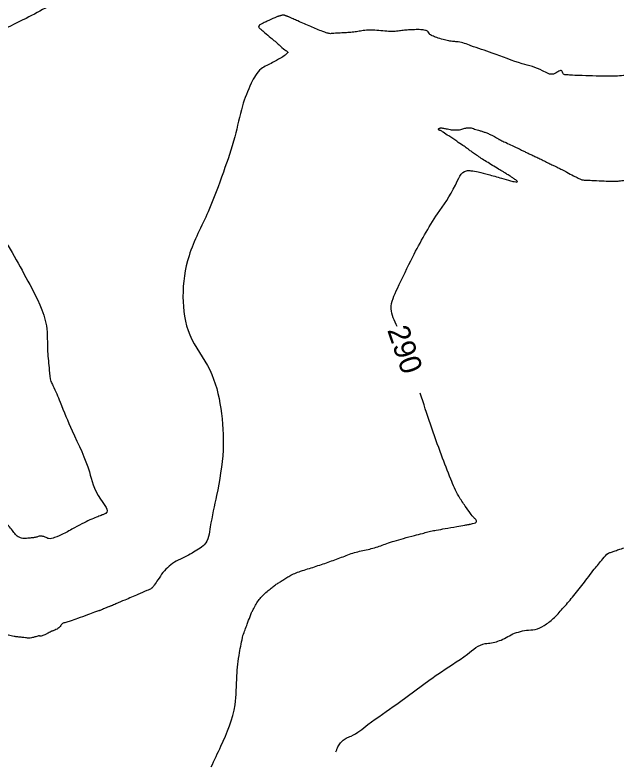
# Model space of a CAD drawing. Extents: x -478102 to -473059, y -1117705 to -1114104.
# Drawn here: x -473738.9 to -473628, y -1115846.1 to -1115707.5 of the extents above; entities that cross this region are included whole.
import ezdxf

# ---------------------------------------------------------------- set-up
doc = ezdxf.new("R2010")
doc.units = 0
for name, color, linetype in [('Vrstevnice_hlavni', 7, 'Continuous'), ('Vrstevnice_popis', 7, 'Continuous'), ('Vrstevnice_vedlejsi', 7, 'Continuous')]:
    doc.layers.add(name, color=color, linetype=linetype)

msp = doc.modelspace()

# ---------------------------------------------------------------- linework, layer by layer
at = {"layer": 'Vrstevnice_hlavni'}
for points in [[(-473628.006, -1115738.135), (-473627.612, -1115738.099), (-473627.098, -1115738.032), (-473626.465, -1115737.934), (-473625.712, -1115737.805), (-473625.126, -1115737.782), (-473624.706, -1115737.864), (-473624.453, -1115738.052), (-473624.056, -1115738.214), (-473623.515, -1115738.351), (-473622.831, -1115738.463), (-473621.977, -1115738.469), (-473620.952, -1115738.369), (-473619.758, -1115738.165), (-473618.673, -1115738.111), (-473617.699, -1115738.207), (-473616.834, -1115738.454), (-473616.07, -1115738.658), (-473615.408, -1115738.821), (-473614.847, -1115738.942), (-473614.352, -1115739.074), (-473613.922, -1115739.217), (-473613.557, -1115739.371), (-473612.986, -1115739.209), (-473612.207, -1115738.733), (-473611.221, -1115737.941), (-473610.493, -1115737.443), (-473610.022, -1115737.238), (-473609.808, -1115737.326), (-473609.65, -1115737.41), (-473609.546, -1115737.488), (-473609.498, -1115737.562), (-473609.448, -1115737.617), (-473609.396, -1115737.653), (-473609.344, -1115737.671), (-473609.284, -1115737.672), (-473609.218, -1115737.658), (-473609.145, -1115737.627), (-473608.356, -1115736.058), (-473606.851, -1115732.95), (-473604.63, -1115728.305), (-473603.008, -1115724.936), (-473601.984, -1115722.844), (-473601.559, -1115722.028), (-473601.248, -1115721.4), (-473601.05, -1115720.96), (-473600.966, -1115720.709), (-473600.877, -1115720.483), (-473600.783, -1115720.283), (-473600.684, -1115720.109), (-473600.609, -1115719.949), (-473600.556, -1115719.804), (-473600.527, -1115719.673), (-473600.49, -1115719.559), (-473600.444, -1115719.462), (-473600.39, -1115719.382), (-473600.339, -1115719.311), (-473600.289, -1115719.249), (-473600.241, -1115719.196), (-473600.189, -1115719.143), (-473600.134, -1115719.089), (-473600.075, -1115719.035), (-473597.757, -1115717.837), (-473593.181, -1115715.494), (-473586.346, -1115712.008), (-473581.479, -1115709.455), (-473578.578, -1115707.835), (-473577.645, -1115707.15), (-473575.166, -1115704.463), (-473571.141, -1115699.773), (-473565.57, -1115693.081), (-473560.969, -1115687.91), (-473557.338, -1115684.26), (-473554.675, -1115682.13), (-473549.56, -1115676.892), (-473541.991, -1115668.546), (-473521.947, -1115645.639)], [(-473668.475, -1115764.94), (-473669.605, -1115761.647), (-473668.466, -1115757.907), (-473665.623, -1115752.073), (-473661.076, -1115744.146), (-473657.776, -1115738.858), (-473655.721, -1115736.21), (-473654.914, -1115736.201), (-473653.575, -1115736.429), (-473651.704, -1115736.894), (-473649.302, -1115737.597), (-473647.612, -1115738.06), (-473646.634, -1115738.281), (-473646.367, -1115738.262), (-473646.375, -1115738.128), (-473646.657, -1115737.88), (-473647.213, -1115737.517), (-473647.682, -1115737.215), (-473648.063, -1115736.972), (-473648.357, -1115736.788), (-473648.938, -1115736.434), (-473649.808, -1115735.909), (-473650.964, -1115735.213), (-473652.028, -1115734.55), (-473652.998, -1115733.922), (-473653.874, -1115733.327), (-473654.6, -1115732.825), (-473655.176, -1115732.414), (-473655.602, -1115732.096), (-473656.384, -1115731.553), (-473657.521, -1115730.786), (-473659.012, -1115729.793), (-473660.021, -1115729.128), (-473660.547, -1115728.79), (-473660.59, -1115728.78), (-473660.64, -1115728.768), (-473660.697, -1115728.755), (-473660.76, -1115728.74), (-473660.811, -1115728.706), (-473660.849, -1115728.655), (-473660.874, -1115728.584), (-473660.891, -1115728.534), (-473660.901, -1115728.503), (-473660.902, -1115728.491), (-473660.859, -1115728.463), (-473660.772, -1115728.42), (-473660.641, -1115728.361), (-473660.545, -1115728.32), (-473660.483, -1115728.298), (-473660.457, -1115728.293), (-473660.122, -1115728.349), (-473659.479, -1115728.466), (-473658.528, -1115728.643), (-473657.634, -1115728.689), (-473656.799, -1115728.604), (-473656.021, -1115728.388), (-473655.373, -1115728.29), (-473654.853, -1115728.309), (-473654.462, -1115728.446), (-473654.01, -1115728.593), (-473653.495, -1115728.749), (-473652.919, -1115728.915), (-473652.323, -1115729.124), (-473651.706, -1115729.374), (-473651.069, -1115729.666), (-473650.567, -1115729.913), (-473650.201, -1115730.115), (-473649.972, -1115730.272), (-473649.799, -1115730.385), (-473649.683, -1115730.454), (-473649.625, -1115730.48), (-473649.21, -1115730.673), (-473648.44, -1115731.034), (-473647.313, -1115731.564), (-473646.364, -1115732.015), (-473645.592, -1115732.388), (-473644.997, -1115732.682), (-473644.364, -1115732.989), (-473643.694, -1115733.307), (-473642.987, -1115733.638), (-473642.226, -1115734.002), (-473641.409, -1115734.399), (-473640.537, -1115734.83), (-473639.818, -1115735.182), (-473639.254, -1115735.457), (-473638.844, -1115735.655), (-473638.166, -1115736), (-473637.219, -1115736.492), (-473636.005, -1115737.132), (-473635.131, -1115737.576), (-473634.598, -1115737.825), (-473634.405, -1115737.877), (-473633.631, -1115737.938), (-473632.275, -1115738.01), (-473630.338, -1115738.09), (-473628.914, -1115738.132), (-473628.006, -1115738.135)], [(-473696.917, -1115821.862), (-473696.136, -1115819.764), (-473695.615, -1115818.364), (-473695.354, -1115817.661), (-473695.352, -1115817.656), (-473695.186, -1115817.356), (-473694.858, -1115816.76), (-473694.366, -1115815.869), (-473693.773, -1115815.046), (-473693.078, -1115814.29), (-473692.282, -1115813.603), (-473691.56, -1115813.018), (-473690.913, -1115812.535), (-473690.34, -1115812.154), (-473689.714, -1115811.749), (-473689.037, -1115811.32), (-473688.307, -1115810.866), (-473687.391, -1115810.43), (-473686.291, -1115810.013), (-473685.005, -1115809.613), (-473683.728, -1115809.204), (-473682.459, -1115808.785), (-473681.2, -1115808.357), (-473679.968, -1115807.915), (-473678.763, -1115807.46), (-473677.585, -1115806.992), (-473676.377, -1115806.594), (-473675.14, -1115806.266), (-473673.873, -1115806.008), (-473672.665, -1115805.697), (-473671.515, -1115805.332), (-473670.424, -1115804.915), (-473669.029, -1115804.461), (-473667.331, -1115803.969), (-473665.33, -1115803.441), (-473663.831, -1115803.046), (-473662.834, -1115802.786), (-473662.341, -1115802.659), (-473661.291, -1115802.45), (-473659.685, -1115802.159), (-473657.523, -1115801.785), (-473656.056, -1115801.531), (-473655.283, -1115801.395), (-473655.205, -1115801.378), (-473654.978, -1115801.323), (-473654.602, -1115801.231), (-473654.077, -1115801.1), (-473653.858, -1115800.887), (-473653.945, -1115800.591), (-473654.338, -1115800.213), (-473655.005, -1115799.355), (-473655.945, -1115798.017), (-473657.159, -1115796.2), (-473658.623, -1115793.079), (-473660.337, -1115788.654), (-473664.268, -1115777.198)], [(-473702.787, -1115846.101), (-473700.971, -1115842.26), (-473698.38, -1115834.653), (-473698.038, -1115829.307), (-473697.55, -1115825.043), (-473696.917, -1115821.862)]]:
    msp.add_spline(points, degree=3, dxfattribs=at)
at = {"layer": 'Vrstevnice_vedlejsi'}
for points in [[(-473633.827, -1115698.259), (-473633.995, -1115698.089), (-473634.23, -1115697.875), (-473634.531, -1115697.615), (-473634.898, -1115697.311), (-473635.37, -1115696.943), (-473635.946, -1115696.512), (-473636.626, -1115696.016), (-473637.283, -1115695.777), (-473637.916, -1115695.795), (-473638.526, -1115696.069), (-473639.188, -1115696.16), (-473639.902, -1115696.067), (-473640.669, -1115695.791), (-473641.217, -1115695.604), (-473641.547, -1115695.506), (-473641.658, -1115695.498), (-473641.786, -1115695.477), (-473641.93, -1115695.443), (-473642.092, -1115695.396), (-473642.453, -1115694.901), (-473643.014, -1115693.955), (-473643.775, -1115692.561), (-473644.339, -1115691.631), (-473644.706, -1115691.167), (-473644.878, -1115691.166), (-473646.367, -1115691.372), (-473649.174, -1115691.783), (-473653.299, -1115692.4), (-473658.302, -1115692.607), (-473664.183, -1115692.403), (-473670.942, -1115691.788), (-473675.569, -1115691.399), (-473678.062, -1115691.235), (-473678.423, -1115691.297), (-473678.805, -1115691.345), (-473679.208, -1115691.38), (-473679.634, -1115691.402), (-473680.115, -1115691.437), (-473680.652, -1115691.486), (-473681.245, -1115691.548), (-473681.804, -1115691.615), (-473682.327, -1115691.685), (-473682.816, -1115691.76), (-473683.401, -1115691.864), (-473684.081, -1115691.997), (-473684.858, -1115692.16), (-473685.679, -1115692.274), (-473686.545, -1115692.337), (-473687.456, -1115692.35), (-473688.562, -1115692.464), (-473689.863, -1115692.678), (-473691.359, -1115692.993), (-473692.754, -1115693.224), (-473694.047, -1115693.371), (-473695.239, -1115693.435), (-473696.867, -1115693.593), (-473698.93, -1115693.846), (-473701.429, -1115694.194), (-473703.483, -1115694.472), (-473705.093, -1115694.682), (-473706.258, -1115694.823), (-473707.349, -1115694.783), (-473708.365, -1115694.561), (-473709.307, -1115694.159), (-473710.077, -1115693.846), (-473710.676, -1115693.62), (-473711.103, -1115693.484), (-473711.702, -1115693.27), (-473712.474, -1115692.98), (-473713.418, -1115692.614), (-473714.211, -1115692.359), (-473714.854, -1115692.217), (-473715.347, -1115692.188), (-473715.74, -1115692.15), (-473716.036, -1115692.105), (-473716.232, -1115692.052), (-473716.416, -1115692.058), (-473716.587, -1115692.125), (-473716.745, -1115692.251), (-473717.14, -1115692.449), (-473717.774, -1115692.717), (-473718.644, -1115693.057), (-473719.102, -1115693.587), (-473719.147, -1115694.306), (-473718.779, -1115695.214), (-473718.469, -1115695.982), (-473718.217, -1115696.61), (-473718.023, -1115697.097), (-473718.112, -1115697.585), (-473718.484, -1115698.074), (-473719.139, -1115698.564), (-473720.229, -1115699.239), (-473721.756, -1115700.099), (-473723.718, -1115701.144), (-473728.761, -1115703.819), (-473736.885, -1115708.126)], [(-473736.885, -1115708.126), (-473748.09, -1115714.063), (-473755.581, -1115718.079), (-473759.357, -1115720.173), (-473759.419, -1115720.346), (-473756.562, -1115724.848), (-473750.785, -1115733.68), (-473742.09, -1115746.84), (-473736.212, -1115757.206), (-473733.15, -1115764.778), (-473732.905, -1115769.555), (-473732.619, -1115772.989), (-473732.294, -1115775.077), (-473731.928, -1115775.821), (-473730.626, -1115778.839), (-473728.388, -1115784.131), (-473725.214, -1115791.696), (-473723.155, -1115796.772), (-473722.21, -1115799.358), (-473722.38, -1115799.453), (-473722.861, -1115799.66), (-473723.653, -1115799.979), (-473724.757, -1115800.409), (-473726.186, -1115801.082), (-473727.942, -1115801.998), (-473730.024, -1115803.157), (-473731.621, -1115803.832), (-473732.733, -1115804.022), (-473733.358, -1115803.727), (-473733.929, -1115803.579), (-473734.443, -1115803.577), (-473734.903, -1115803.722), (-473735.531, -1115803.839), (-473736.329, -1115803.931), (-473737.296, -1115803.995), (-473738.129, -1115803.776), (-473738.829, -1115803.274), (-473739.395, -1115802.488), (-473740.125, -1115801.665), (-473741.02, -1115800.805), (-473742.08, -1115799.908), (-473743.23, -1115799.265), (-473744.471, -1115798.874), (-473745.803, -1115798.738), (-473746.741, -1115798.646), (-473747.284, -1115798.6), (-473747.433, -1115798.6), (-473747.65, -1115798.58), (-473747.934, -1115798.539), (-473748.285, -1115798.478), (-473748.767, -1115798.655), (-473749.38, -1115799.07), (-473750.123, -1115799.723), (-473750.726, -1115800.236), (-473751.186, -1115800.608), (-473751.506, -1115800.838), (-473752.388, -1115800.662), (-473753.831, -1115800.08), (-473755.837, -1115799.09), (-473758.181, -1115797.917), (-473760.863, -1115796.56), (-473763.884, -1115795.021), (-473766.014, -1115793.92), (-473767.255, -1115793.257), (-473767.606, -1115793.033), (-473768.384, -1115792.504), (-473769.588, -1115791.67), (-473771.218, -1115790.531), (-473772.894, -1115789.612), (-473774.616, -1115788.914), (-473776.384, -1115788.436), (-473778.175, -1115788.351), (-473779.988, -1115788.658), (-473781.825, -1115789.358), (-473783.761, -1115789.804), (-473785.796, -1115789.996), (-473787.932, -1115789.933), (-473790.24, -1115789.962), (-473792.721, -1115790.082), (-473795.375, -1115790.292), (-473798.082, -1115790.485), (-473800.842, -1115790.659), (-473803.656, -1115790.816), (-473805.574, -1115790.922), (-473806.597, -1115790.978), (-473806.725, -1115790.983), (-473806.818, -1115790.988), (-473806.878, -1115790.99), (-473806.903, -1115790.991), (-473807.545, -1115790.98), (-473808.802, -1115790.958), (-473810.676, -1115790.923), (-473812.576, -1115790.887), (-473814.501, -1115790.848), (-473816.452, -1115790.809), (-473818.119, -1115790.836), (-473819.503, -1115790.932)], [(-473691.064, -1115708.023), (-473691.409, -1115708.174), (-473691.88, -1115708.387), (-473692.476, -1115708.662), (-473693.198, -1115709), (-473693.68, -1115709.247), (-473693.923, -1115709.404), (-473693.925, -1115709.47), (-473693.945, -1115709.533), (-473693.98, -1115709.593), (-473694.033, -1115709.651), (-473693.988, -1115709.76), (-473693.846, -1115709.921), (-473693.606, -1115710.133), (-473692.924, -1115710.722), (-473691.8, -1115711.686), (-473690.233, -1115713.028), (-473689.187, -1115713.927), (-473688.661, -1115714.383), (-473688.655, -1115714.398), (-473688.735, -1115714.488), (-473688.9, -1115714.655), (-473689.149, -1115714.899), (-473690.007, -1115715.442), (-473691.473, -1115716.286), (-473693.546, -1115717.429), (-473695.395, -1115720.087), (-473697.017, -1115724.258), (-473698.415, -1115729.943), (-473700.519, -1115736.441), (-473703.332, -1115743.752), (-473706.852, -1115751.876), (-473707.978, -1115759.446), (-473706.71, -1115766.462), (-473703.048, -1115772.924), (-473701.007, -1115780.007), (-473700.587, -1115787.711), (-473701.787, -1115796.036), (-473702.939, -1115801.847), (-473704.042, -1115805.146), (-473705.098, -1115805.933), (-473706.309, -1115806.697), (-473707.677, -1115807.441), (-473709.202, -1115808.164), (-473710.531, -1115809.101), (-473711.664, -1115810.254), (-473712.602, -1115811.622), (-473713.262, -1115812.565), (-473713.646, -1115813.083), (-473713.753, -1115813.175), (-473714.627, -1115813.582), (-473716.266, -1115814.302), (-473718.673, -1115815.337), (-473720.319, -1115816.042), (-473721.205, -1115816.416), (-473721.33, -1115816.46), (-473721.503, -1115816.526), (-473721.723, -1115816.612), (-473721.989, -1115816.72), (-473722.284, -1115816.843), (-473722.607, -1115816.979), (-473722.958, -1115817.131), (-473723.234, -1115817.243), (-473723.434, -1115817.316), (-473723.559, -1115817.349), (-473724.262, -1115817.6), (-473725.545, -1115818.067), (-473727.406, -1115818.75), (-473728.752, -1115819.224), (-473729.582, -1115819.488), (-473729.896, -1115819.543), (-473730.167, -1115819.679), (-473730.394, -1115819.896), (-473730.578, -1115820.195), (-473730.841, -1115820.457), (-473731.183, -1115820.68), (-473731.604, -1115820.865), (-473731.894, -1115820.987), (-473732.053, -1115821.046), (-473732.08, -1115821.042), (-473732.104, -1115821.045), (-473732.127, -1115821.057), (-473732.149, -1115821.076), (-473732.176, -1115821.095), (-473732.209, -1115821.111), (-473732.249, -1115821.127), (-473732.296, -1115821.151), (-473732.352, -1115821.184), (-473732.415, -1115821.226), (-473732.62, -1115821.331), (-473732.967, -1115821.499), (-473733.455, -1115821.73), (-473733.824, -1115821.886), (-473734.072, -1115821.966), (-473734.2, -1115821.97), (-473734.308, -1115821.967), (-473734.394, -1115821.959)], [(-473616.014, -1115725.235), (-473615.857, -1115725.677), (-473615.796, -1115726.269), (-473615.833, -1115727.01), (-473615.967, -1115727.901), (-473616.206, -1115728.377), (-473616.55, -1115728.44), (-473617, -1115728.088), (-473617.357, -1115727.757), (-473617.622, -1115727.449), (-473617.794, -1115727.162), (-473618.117, -1115726.847), (-473618.588, -1115726.504), (-473619.209, -1115726.133), (-473619.785, -1115725.717), (-473620.315, -1115725.254), (-473620.799, -1115724.746), (-473621.223, -1115724.099), (-473621.587, -1115723.313), (-473621.89, -1115722.388), (-473622.23, -1115721.609), (-473622.606, -1115720.976), (-473623.019, -1115720.489), (-473623.47, -1115720.005), (-473623.959, -1115719.525), (-473624.486, -1115719.049), (-473625.317, -1115718.763), (-473626.452, -1115718.668), (-473627.89, -1115718.764), (-473629.695, -1115718.797), (-473631.864, -1115718.766), (-473634.4, -1115718.672), (-473636.201, -1115718.602), (-473637.267, -1115718.556), (-473637.599, -1115718.533), (-473637.846, -1115718.415), (-473638.008, -1115718.2), (-473638.084, -1115717.89), (-473638.256, -1115717.748), (-473638.522, -1115717.776), (-473638.884, -1115717.972), (-473639.203, -1115718.138), (-473639.479, -1115718.274), (-473639.712, -1115718.379), (-473641.705, -1115717.786), (-473645.458, -1115716.496), (-473650.971, -1115714.508), (-473654.913, -1115713.164), (-473657.284, -1115712.462), (-473658.082, -1115712.402), (-473659.003, -1115712.251), (-473660.045, -1115712.007), (-473661.208, -1115711.672), (-473662.051, -1115711.323), (-473662.576, -1115710.96), (-473662.781, -1115710.584), (-473663.307, -1115710.333), (-473664.152, -1115710.207), (-473665.319, -1115710.207), (-473666.403, -1115710.253), (-473667.407, -1115710.344), (-473668.329, -1115710.482), (-473669.448, -1115710.529), (-473670.763, -1115710.483), (-473672.274, -1115710.345), (-473673.607, -1115710.309), (-473674.761, -1115710.375), (-473675.736, -1115710.542), (-473676.769, -1115710.672), (-473677.86, -1115710.767), (-473679.009, -1115710.826), (-473679.883, -1115710.876), (-473680.482, -1115710.918), (-473680.806, -1115710.952), (-473681.385, -1115710.829), (-473682.22, -1115710.547), (-473683.31, -1115710.108), (-473684.44, -1115709.637), (-473685.61, -1115709.135), (-473686.82, -1115708.603), (-473687.699, -1115708.212), (-473688.249, -1115707.964), (-473688.468, -1115707.858), (-473688.649, -1115707.779), (-473688.791, -1115707.728), (-473688.895, -1115707.703), (-473689.012, -1115707.667), (-473689.142, -1115707.618), (-473689.286, -1115707.557), (-473689.464, -1115707.533), (-473689.675, -1115707.548), (-473689.919, -1115707.6), (-473690.144, -1115707.659), (-473690.349, -1115707.725), (-473690.534, -1115707.799), (-473690.772, -1115707.898), (-473691.064, -1115708.023)], [(-473679.794, -1115843.292), (-473679.6, -1115842.797), (-473679.201, -1115841.998), (-473678.635, -1115841.332), (-473677.902, -1115840.799), (-473677.003, -1115840.4), (-473673.886, -1115838.3), (-473668.551, -1115834.5), (-473660.998, -1115829.001), (-473655.575, -1115825.291), (-473652.282, -1115823.372), (-473651.118, -1115823.244), (-473649.936, -1115822.929), (-473648.738, -1115822.43), (-473647.522, -1115821.744), (-473646.174, -1115821.234), (-473644.693, -1115820.901), (-473643.08, -1115820.743), (-473641.431, -1115820.027), (-473639.747, -1115818.754), (-473638.027, -1115816.924), (-473636.192, -1115814.795), (-473634.242, -1115812.366), (-473632.177, -1115809.638), (-473630.62, -1115807.751), (-473629.571, -1115806.704), (-473629.03, -1115806.498), (-473628.323, -1115806.249), (-473627.449, -1115805.956), (-473626.408, -1115805.62), (-473625.521, -1115805.327), (-473624.788, -1115805.079), (-473624.208, -1115804.874), (-473623.753, -1115804.715), (-473623.421, -1115804.603), (-473623.214, -1115804.536), (-473623.011, -1115804.465), (-473622.813, -1115804.389), (-473622.618, -1115804.307), (-473622.291, -1115803.919), (-473621.832, -1115803.225), (-473621.241, -1115802.223), (-473620.844, -1115801.552), (-473620.642, -1115801.212), (-473620.635, -1115801.204), (-473620.179, -1115800.264), (-473619.274, -1115798.394), (-473617.92, -1115795.593), (-473617.015, -1115793.724), (-473616.561, -1115792.788), (-473616.556, -1115792.783), (-473614.969, -1115790.321), (-473611.8, -1115785.401)], [(-473734.394, -1115821.959), (-473734.459, -1115821.944), (-473734.694, -1115821.989), (-473735.101, -1115822.092), (-473735.678, -1115822.254), (-473736.119, -1115822.349), (-473736.424, -1115822.378), (-473736.594, -1115822.34), (-473736.979, -1115822.287), (-473737.58, -1115822.219), (-473738.396, -1115822.137), (-473739.089, -1115822.044), (-473739.66, -1115821.939), (-473740.108, -1115821.822), (-473740.484, -1115821.711), (-473740.786, -1115821.606), (-473741.016, -1115821.507), (-473741.223, -1115821.428), (-473741.409, -1115821.369), (-473741.574, -1115821.329), (-473742.241, -1115821.266), (-473743.412, -1115821.178), (-473745.087, -1115821.067), (-473746.466, -1115820.955), (-473747.55, -1115820.842), (-473748.339, -1115820.729), (-473749.038, -1115820.405), (-473749.647, -1115819.869), (-473750.166, -1115819.123), (-473750.684, -1115818.549), (-473751.201, -1115818.149), (-473751.717, -1115817.921), (-473752.194, -1115817.702), (-473752.633, -1115817.492), (-473753.032, -1115817.29), (-473753.509, -1115816.946), (-473754.061, -1115816.458), (-473754.69, -1115815.827), (-473755.285, -1115815.362), (-473755.844, -1115815.062), (-473756.369, -1115814.927), (-473757.778, -1115814.293), (-473760.07, -1115813.16), (-473763.246, -1115811.529), (-473765.617, -1115810.379), (-473767.184, -1115809.712), (-473767.947, -1115809.527), (-473768.842, -1115809.244), (-473769.869, -1115808.862), (-473771.029, -1115808.383), (-473772.007, -1115807.964), (-473772.803, -1115807.608), (-473773.418, -1115807.312), (-473774.925, -1115806.592), (-473777.324, -1115805.448), (-473780.616, -1115803.88), (-473782.979, -1115802.662), (-473784.413, -1115801.794), (-473784.918, -1115801.277), (-473785.429, -1115800.905), (-473785.945, -1115800.678), (-473786.467, -1115800.596), (-473786.999, -1115800.574), (-473787.541, -1115800.614), (-473788.093, -1115800.715), (-473788.871, -1115800.801), (-473789.874, -1115800.871), (-473791.101, -1115800.925), (-473792.016, -1115801.057), (-473792.618, -1115801.268), (-473792.907, -1115801.556), (-473793.168, -1115801.85), (-473793.399, -1115802.15), (-473793.602, -1115802.456), (-473794.297, -1115802.729), (-473795.483, -1115802.97), (-473797.16, -1115803.178), (-473798.682, -1115803.46), (-473800.047, -1115803.815), (-473801.256, -1115804.244), (-473802.295, -1115804.656), (-473803.164, -1115805.051), (-473803.864, -1115805.43), (-473805.001, -1115805.754), (-473806.575, -1115806.023), (-473808.588, -1115806.238), (-473810.308, -1115806.503), (-473811.737, -1115806.819), (-473812.874, -1115807.186), (-473814.744, -1115808.011), (-473817.346, -1115809.295), (-473820.682, -1115811.036), (-473823.145, -1115812.534), (-473824.735, -1115813.788), (-473825.453, -1115814.798), (-473826.149, -1115815.894), (-473826.822, -1115817.077)]]:
    msp.add_spline(points, degree=3, dxfattribs=at)

# ---------------------------------------------------------------- texts
at = {"layer": 'Vrstevnice_popis'}
msp.add_text(' 290 ', height=4, rotation=288.93926, dxfattribs=at).set_placement((-473670.861, -1115764.149))

doc.saveas('drawing.dxf')
